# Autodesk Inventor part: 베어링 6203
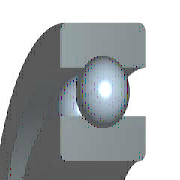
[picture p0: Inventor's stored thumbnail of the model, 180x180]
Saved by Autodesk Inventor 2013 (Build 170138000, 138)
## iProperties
IsCustomPart: 0
Created: 2016-04
Part Number: 베어링 6203
Material: 강철, 연강
Description: 깊은 그루브 볼 베어링
Document SubType Name: Modeling
Standard: KS B 2023
Designer: mdu
Standards Organization: KS
Language: ko-KR
Size Designation: 6203 - 17 x 40 x 12
Categories: <MemberInstance><Categories><Category DisplayName="샤프트 부품" InternalName="7f7aeb1f-a693-4053-b835-cee3144e0d98" Mnemonic="SHFT"><Category DisplayName="베어링" Inter
Density: 2.71 g/cm^3
Mass: 22.4044 g
Surface Area: 64.3582 cm^2
Volume: 8.26729 cm^3
Author: mdu
Revision Number: 1
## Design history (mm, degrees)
sketch "스케치" dims "d0" = 5.98 (= -0.26 x WD + 0.26 x BD)
  geometry: L1 (3.01, 14.25)-(8.99, 14.25); L2 (6, 14.25)-(6, 11.26); L3 (6, 14.25)-(6, 17.24); L4 (3.778, 12.249)-(0, 12.249); L5 (0, 8.5)-(12, 8.5); L6 (3.778, 16.251)-(0, 16.251); L7 (0, 20)-(12, 20); L8 (12, 8.5)-(12, 12.249); L9 (8.222, 12.249)-(12, 12.249); L10 (8.222, 16.251)-(12, 16.251); L11 (12, 20)-(12, 16.251); L12 (-1.4, 0)-(8.4, 0) reference; L13 (0, -0.3)-(0, 5.3) reference
  constraints: 22 end point, 4 point on line, 2 collinear, 2 perpendicular, 2 symmetric about line, 1 midpoint, 1 parallel, 14 other
  dimensions: "d9" = 17 diameter of L5 L12 (= WD); "d11" = 40 diameter of L7 L12 (= BD); "d12" = 12 distance between parallel lines of L8 L13 (= KB); "d13" = 24.498 diameter of L9 L12 (= 0.326 x BD + 0.674 x WD)
revolve "본체" stored, may be unused: angle "d6" = 90 deg
revolve "볼" stored, may be unused: angle "d7" = 90 deg
pattern_circular "IDS_ARRAYBALL[SIMPL:T]" dims angle "d3" = 360 deg
body "Solid1"
fillet "모깎기1" dims "d1" = 0.6 (= KRS)
other parameters: "WD" = 17 [user parameter; used in 5 equation terms], "BD" = 40 [user parameter; used in 5 equation terms], "KB" = 12 [user parameter; used in 1 equation term], "KRS" = 0.6 [user parameter; used in 1 equation term], "d4" = 0, "d5" = 0, "d8" = 0, "d14" = 0, "d15" = 0, "BBA" = 0 [user parameter], "BC0" = 4750000 [user parameter], "BC" = 9560000 [user parameter], "WR" = 8.5 (= 0.5 x WD) [user parameter]
